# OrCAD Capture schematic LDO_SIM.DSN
size A
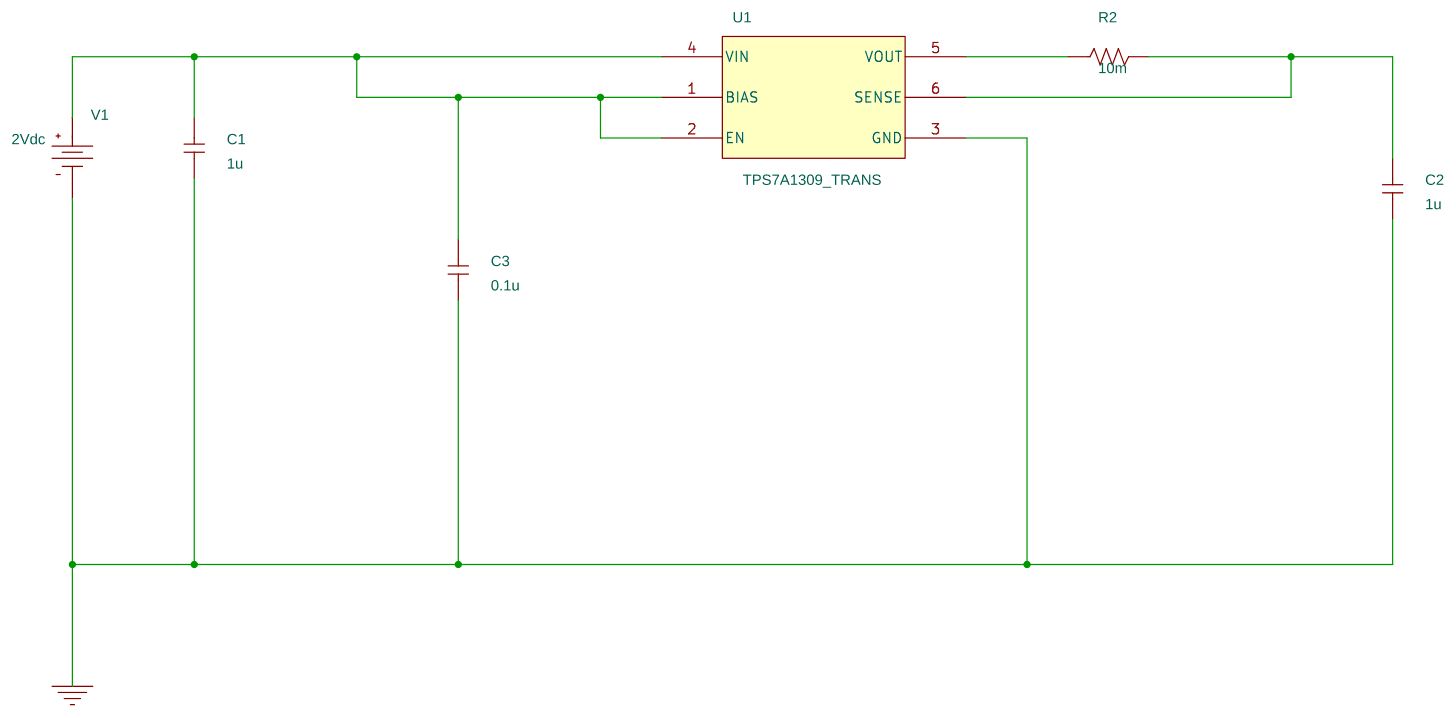
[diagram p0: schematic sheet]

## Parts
C1  1u  [cap196]
C2  1u  [cap196]
C3  0.1u  [cap196]
R2  10m  [AXRC05]
U1  TPS7A1309_TRANS
V1  VDC

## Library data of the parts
C1-C3 = C: PSPNETLIST_IGNORE: TRUE
R2 = R: PSPNETLIST_IGNORE: TRUE
U1 = TPS7A1309_TRANS_0: PSPNETLIST_IGNORE: TRUE
V1 = VDC: DC: 2Vdc; PSPNETLIST_IGNORE: TRUE

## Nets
0: C1.1 C2.1 C3.1 U1.3(GND) V1.1(-)
N00135: C1.2 C3.2 U1.1(BIAS) U1.2(EN) U1.4(VIN) V1.0(+)
N00292: C2.2 R2.2 U1.6(SENSE)
N03326: R2.1 U1.5(VOUT)
